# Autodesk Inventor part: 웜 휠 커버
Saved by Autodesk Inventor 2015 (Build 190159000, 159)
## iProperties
Created: 2025-06
Part Number: 웜 휠 커버
Material: 일반
Document SubType Name: Modeling
Designer: 104
Density: 1 g/cm^3
Appearance: 기본값
Author: 104
Author: jhkim
Creation Date: 2025-05-23
Sending System: Autodesk Inventor 2026
Preprocessor: ST-DEVELOPER v20.1
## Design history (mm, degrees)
node "웜 휠 커버1"
node "솔리드1"
node "기준1"
